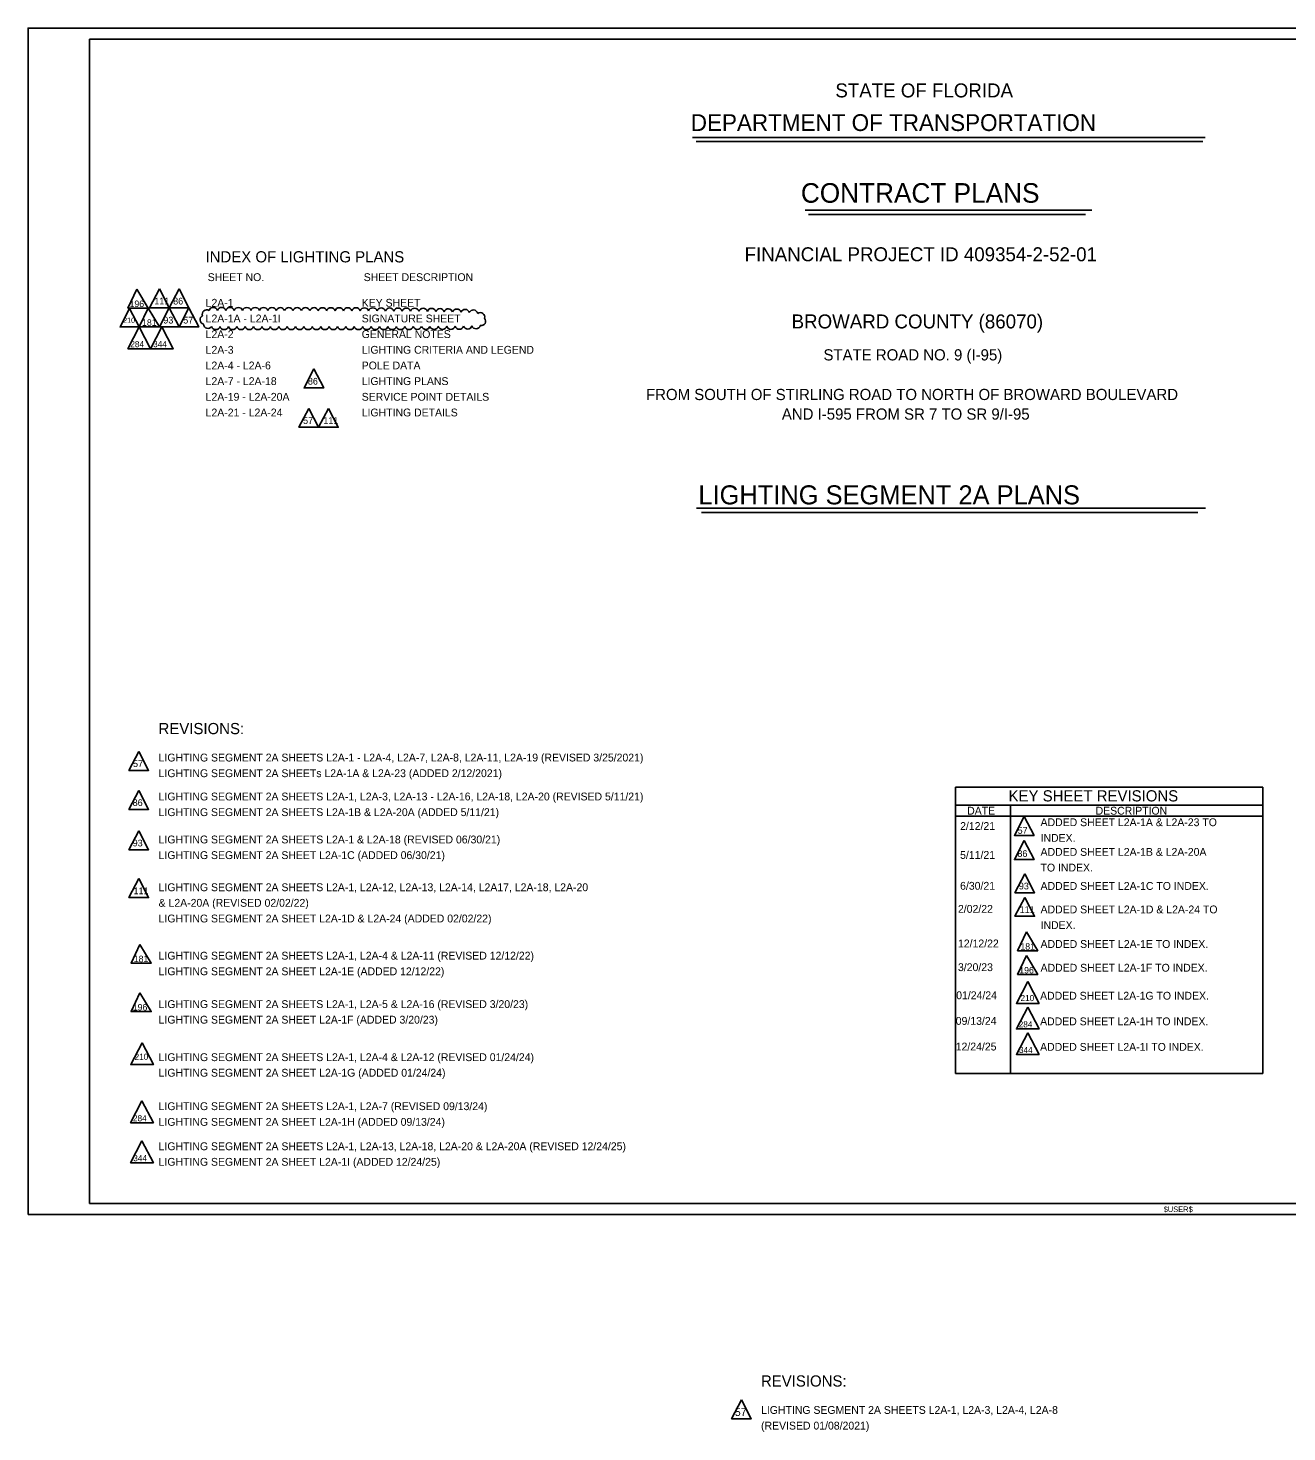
# Model space of a CAD drawing. Extents: x -820.2 to -798.7, y -2201.1 to -2188.5.
# Drawn here: x -820.23 to -808.98, y -2201.07 to -2188.52 of the extents above; entities that cross this region are included whole.
import ezdxf

# ---------------------------------------------------------------- set-up
doc = ezdxf.new("R2010")
doc.units = 0
for name, color, linetype in [('AdhocPoint_dp', 7, 'Continuous'), ('Cloud_dp', 7, 'Continuous'), ('PlotBorder_dp', 7, 'Continuous'), ('SheetBorder_dp', 7, 'Continuous'), ('SumBoxLines_dp', 7, 'Continuous'), ('TextLabel', 7, 'Continuous'), ('TextMinor', 7, 'Continuous'), ('TextNotes', 7, 'Continuous'), ('TextTitle', 7, 'Continuous')]:
    doc.layers.add(name, color=color, linetype=linetype)

msp = doc.modelspace()

# ---------------------------------------------------------------- linework, layer by layer
at = {"layer": 'AdhocPoint_dp'}
msp.add_line((-820.227, -2199.124), (-820.227, -2199.124), dxfattribs=at)
at = {"layer": 'Cloud_dp'}
for points in [[(-819.256, -2190.857), (-819.335, -2191.025), (-819.155, -2191.025)], [(-819.053, -2190.854), (-819.141, -2191.023), (-818.965, -2191.023)], [(-818.877, -2190.854), (-818.965, -2191.023), (-818.789, -2191.023)], [(-819.319, -2191.028), (-819.405, -2191.193), (-819.234, -2191.193)], [(-819.155, -2191.025), (-819.234, -2191.193), (-819.053, -2191.193)], [(-818.965, -2191.023), (-819.053, -2191.193), (-818.877, -2191.193)], [(-818.789, -2191.023), (-818.877, -2191.193), (-818.701, -2191.193)], [(-819.234, -2191.193), (-819.335, -2191.388), (-819.132, -2191.388)], [(-819.031, -2191.193), (-819.132, -2191.388), (-818.93, -2191.388)], [(-817.672, -2191.569), (-817.76, -2191.739), (-817.584, -2191.739)], [(-817.718, -2191.921), (-817.806, -2192.09), (-817.63, -2192.09)], [(-817.542, -2191.921), (-817.63, -2192.09), (-817.454, -2192.09)], [(-819.238, -2194.986), (-819.326, -2195.156), (-819.15, -2195.156)], [(-819.238, -2195.335), (-819.326, -2195.504), (-819.15, -2195.504)], [(-811.324, -2195.567), (-811.412, -2195.736), (-811.236, -2195.736)], [(-819.238, -2195.696), (-819.326, -2195.865), (-819.15, -2195.865)], [(-811.324, -2195.783), (-811.412, -2195.953), (-811.236, -2195.953)], [(-811.319, -2196.08), (-811.407, -2196.249), (-811.231, -2196.249)], [(-819.238, -2196.123), (-819.326, -2196.292), (-819.15, -2196.292)], [(-811.319, -2196.29), (-811.407, -2196.459), (-811.231, -2196.459)], [(-819.228, -2196.71), (-819.307, -2196.878), (-819.126, -2196.878)], [(-811.305, -2196.599), (-811.384, -2196.767), (-811.203, -2196.767)], [(-811.305, -2196.811), (-811.384, -2196.979), (-811.203, -2196.979)], [(-811.293, -2197.042), (-811.394, -2197.237), (-811.191, -2197.237)], [(-819.228, -2197.142), (-819.307, -2197.31), (-819.126, -2197.31)], [(-811.293, -2197.27), (-811.394, -2197.465), (-811.191, -2197.465)], [(-819.207, -2197.589), (-819.309, -2197.784), (-819.106, -2197.784)], [(-811.293, -2197.499), (-811.394, -2197.694), (-811.191, -2197.694)], [(-819.209, -2198.109), (-819.31, -2198.304), (-819.107, -2198.304)], [(-819.209, -2198.466), (-819.31, -2198.661), (-819.107, -2198.661)], [(-813.851, -2200.779), (-813.939, -2200.949), (-813.763, -2200.949)]]:
    msp.add_lwpolyline(points, close=True, dxfattribs=at)
for centre, radius, start, end in [((-818.631, -2191.079), 0.0393, 57.4429, 202.4429), ((-818.572, -2191.058), 0.0393, 17.4254, 162.4254), ((-818.497, -2191.058), 0.0393, 17.3487, 162.3487), ((-818.422, -2191.058), 0.0393, 17.3487, 162.3487), ((-818.347, -2191.059), 0.0393, 17.3487, 162.3487), ((-818.272, -2191.059), 0.0393, 17.3487, 162.3487), ((-818.197, -2191.059), 0.0393, 17.3487, 162.3487), ((-818.122, -2191.059), 0.0393, 17.3487, 162.3487), ((-818.047, -2191.059), 0.0393, 17.3487, 162.3487), ((-817.972, -2191.06), 0.0393, 17.3487, 162.3487), ((-817.897, -2191.06), 0.0393, 17.3487, 162.3487), ((-817.822, -2191.06), 0.0393, 17.3487, 162.3487), ((-817.747, -2191.06), 0.0393, 17.3487, 162.3487), ((-817.671, -2191.06), 0.0393, 17.3487, 162.3487), ((-817.596, -2191.061), 0.0393, 17.3487, 162.3487), ((-817.521, -2191.061), 0.0393, 17.3487, 162.3487), ((-817.446, -2191.061), 0.0393, 17.3487, 162.3487), ((-817.371, -2191.061), 0.0393, 17.3304, 162.3304), ((-817.296, -2191.061), 0.0393, 17.2888, 162.2888), ((-817.221, -2191.062), 0.0393, 17.2428, 162.2428), ((-817.146, -2191.062), 0.0393, 17.1914, 162.1914), ((-817.071, -2191.063), 0.0393, 17.1336, 162.1336), ((-816.996, -2191.063), 0.0393, 17.0679, 162.0679), ((-816.921, -2191.064), 0.0393, 16.9923, 161.9923), ((-816.846, -2191.064), 0.0393, 16.904, 161.904), ((-816.771, -2191.065), 0.0393, 16.799, 161.799), ((-816.696, -2191.066), 0.0393, 16.6713, 161.6713), ((-816.621, -2191.067), 0.0393, 16.5114, 161.5114), ((-816.546, -2191.069), 0.0393, 16.3028, 161.3028), ((-816.471, -2191.071), 0.0393, 16.0143, 161.0143), ((-816.396, -2191.073), 0.0393, 15.5766, 160.5766), ((-816.321, -2191.076), 0.0393, 14.7862, 159.7862), ((-816.247, -2191.081), 0.0394, 12.403, 157.403), ((-816.185, -2191.104), 0.0393, 341.3099, 126.3099), ((-818.651, -2191.13), 0.0393, 113.8298, 258.8298), ((-818.619, -2191.168), 0.0393, 180.98, 325.98), ((-818.549, -2191.178), 0.0393, 197.5, 342.5), ((-818.474, -2191.178), 0.0393, 197.5, 342.5), ((-818.399, -2191.178), 0.0393, 197.5, 342.5), ((-818.324, -2191.178), 0.0393, 197.5, 342.5), ((-818.249, -2191.178), 0.0393, 197.5, 342.5), ((-818.174, -2191.178), 0.0393, 197.5, 342.5), ((-818.099, -2191.178), 0.0393, 197.5, 342.5), ((-818.024, -2191.178), 0.0393, 197.5, 342.5), ((-817.949, -2191.178), 0.0393, 197.5, 342.5), ((-817.874, -2191.178), 0.0393, 197.5, 342.5), ((-817.799, -2191.178), 0.0393, 197.5, 342.5), ((-817.724, -2191.178), 0.0393, 197.5, 342.5), ((-817.649, -2191.178), 0.0393, 197.5, 342.5), ((-817.574, -2191.178), 0.0393, 197.5, 342.5), ((-817.499, -2191.178), 0.0393, 197.5, 342.5), ((-817.424, -2191.178), 0.0393, 197.5, 342.5), ((-817.349, -2191.178), 0.0393, 197.5052, 342.5052), ((-817.274, -2191.178), 0.0393, 197.5223, 342.5223), ((-817.199, -2191.178), 0.0393, 197.5417, 342.5417), ((-817.123, -2191.178), 0.0393, 197.5633, 342.5633), ((-817.048, -2191.178), 0.0393, 197.5876, 342.5876), ((-816.973, -2191.178), 0.0393, 197.6153, 342.6153), ((-816.898, -2191.178), 0.0393, 197.6471, 342.6471), ((-816.823, -2191.178), 0.0393, 197.6843, 342.6843), ((-816.748, -2191.177), 0.0393, 197.7285, 342.7285), ((-816.673, -2191.177), 0.0393, 197.7822, 342.7822), ((-816.598, -2191.177), 0.0393, 197.8496, 342.8496), ((-816.523, -2191.176), 0.0393, 197.9376, 342.9376), ((-816.448, -2191.176), 0.0393, 198.0595, 343.0595), ((-816.373, -2191.175), 0.0393, 198.2448, 343.2448), ((-816.298, -2191.173), 0.0393, 198.5811, 343.5811), ((-816.223, -2191.171), 0.0394, 199.6227, 344.6227), ((-816.177, -2191.143), 0.0393, 257.5478, 42.5478)]:
    msp.add_arc(centre, radius, start, end, dxfattribs=at)
at = {"layer": 'PlotBorder_dp'}
msp.add_lwpolyline([(-820.227, -2199.124), (-803.727, -2199.124), (-803.727, -2188.524), (-820.227, -2188.524)], close=True, dxfattribs=at)
at = {"layer": 'SheetBorder_dp'}
for p, q in [((-819.677, -2188.624), (-819.677, -2199.024)), ((-819.677, -2188.624), (-804.277, -2188.624)), ((-819.677, -2199.024), (-804.277, -2199.024))]:
    msp.add_line(p, q, dxfattribs=at)
at = {"layer": 'SumBoxLines_dp'}
for p, q in [((-811.938, -2195.306), (-811.938, -2197.863)), ((-811.938, -2195.306), (-809.191, -2195.306)), ((-809.191, -2195.306), (-809.191, -2197.863)), ((-811.938, -2195.466), (-809.191, -2195.466)), ((-811.938, -2195.566), (-809.191, -2195.566)), ((-811.448, -2195.466), (-811.448, -2197.863)), ((-811.938, -2197.863), (-809.191, -2197.863))]:
    msp.add_line(p, q, dxfattribs=at)
at = {"layer": 'TextTitle'}
for p, q in [((-814.289, -2189.5), (-809.707, -2189.5)), ((-814.257, -2189.538), (-809.729, -2189.538)), ((-813.281, -2190.15), (-810.719, -2190.15)), ((-813.253, -2190.188), (-810.777, -2190.188)), ((-814.252, -2192.813), (-809.704, -2192.813)), ((-814.209, -2192.851), (-809.772, -2192.851))]:
    msp.add_line(p, q, dxfattribs=at)

# ---------------------------------------------------------------- texts
at = {"layer": 'Cloud_dp'}
for s, height, p in [('111', 0.06, (-819.099, -2190.993)), ('86', 0.06, (-818.93, -2190.993)), ('93', 0.06, (-819.018, -2191.163)), ('57', 0.06, (-818.84, -2191.163)), ('86', 0.06, (-817.726, -2191.709)), ('57', 0.06, (-817.769, -2192.06)), ('111', 0.06, (-817.588, -2192.06)), ('57', 0.06, (-819.289, -2195.126)), ('86', 0.06, (-819.292, -2195.474)), ('57', 0.06, (-811.383, -2195.722)), ('93', 0.06, (-819.292, -2195.835)), ('86', 0.06, (-811.385, -2195.929)), ('111', 0.06, (-819.284, -2196.262)), ('93', 0.06, (-811.372, -2196.219)), ('111', 0.06, (-811.364, -2196.429)), ('57', 0.07, (-813.91, -2200.924))]:
    msp.add_text(s, height=height, rotation=0, dxfattribs=at).set_placement(p)
for s, height, p in [('196', 0.0582, (-819.32, -2191.016)), ('210', 0.0461, (-819.377, -2191.157)), ('181', 0.0582, (-819.208, -2191.184)), ('284', 0.0547, (-819.313, -2191.375)), ('344', 0.0547, (-819.109, -2191.375)), ('181', 0.0582, (-811.358, -2196.758)), ('181', 0.0582, (-819.282, -2196.869)), ('196', 0.0582, (-811.368, -2196.97)), ('210', 0.0547, (-811.357, -2197.217)), ('196', 0.0582, (-819.291, -2197.301)), ('284', 0.0547, (-811.373, -2197.452)), ('210', 0.0547, (-819.275, -2197.742)), ('344', 0.0547, (-811.371, -2197.681)), ('284', 0.0547, (-819.289, -2198.291)), ('344', 0.0547, (-819.287, -2198.648))]:
    msp.add_text(s, height=height, dxfattribs=at).set_placement(p)
at = {"layer": 'TextLabel'}
for s, height, p in [('INDEX OF LIGHTING PLANS', 0.1, (-818.641, -2190.617)), ('FINANCIAL PROJECT ID 409354-2-52-01', 0.125, (-813.823, -2190.607)), ('L2A-1', 0.07, (-818.64, -2191.013)), ('KEY SHEET', 0.07, (-817.245, -2191.013)), ('L2A-1A - L2A-1I', 0.07, (-818.64, -2191.153)), ('SIGNATURE SHEET', 0.07, (-817.245, -2191.153)), ('BROWARD COUNTY (86070)', 0.125, (-813.403, -2191.207)), ('L2A-2', 0.07, (-818.64, -2191.293)), ('GENERAL NOTES', 0.07, (-817.245, -2191.293)), ('L2A-3', 0.07, (-818.64, -2191.433)), ('LIGHTING CRITERIA AND LEGEND', 0.07, (-817.245, -2191.433)), ('STATE ROAD NO. 9 (I-95)', 0.1, (-813.118, -2191.493)), ('L2A-4 - L2A-6 ', 0.07, (-818.64, -2191.573)), ('POLE DATA', 0.07, (-817.245, -2191.573)), ('L2A-7 - L2A-18', 0.07, (-818.64, -2191.713)), ('LIGHTING PLANS', 0.07, (-817.245, -2191.713)), ('L2A-19 - L2A-20A', 0.07, (-818.64, -2191.853)), ('SERVICE POINT DETAILS', 0.07, (-817.245, -2191.853)), ('FROM SOUTH OF STIRLING ROAD TO NORTH OF BROWARD BOULEVARD', 0.1, (-814.704, -2191.847)), ('L2A-21 - L2A-24', 0.07, (-818.64, -2191.993)), ('LIGHTING DETAILS', 0.07, (-817.245, -2191.993)), ('AND I-595 FROM SR 7 TO SR 9/I-95', 0.1, (-813.49, -2192.022)), ('REVISIONS:', 0.1, (-819.061, -2194.832)), ('KEY SHEET REVISIONS', 0.1, (-811.464, -2195.433)), ('REVISIONS:', 0.1, (-813.677, -2200.661))]:
    msp.add_text(s, height=height, dxfattribs=at).set_placement(p)
at = {"layer": 'TextMinor'}
for s, height, p in [('ADDED SHEET L2A-1A & L2A-23 TO ', 0.07, (-811.178, -2195.654)), ('2/12/21', 0.07, (-811.897, -2195.688)), ('INDEX.', 0.07, (-811.178, -2195.794)), ('5/11/21', 0.07, (-811.897, -2195.946)), ('ADDED SHEET L2A-1B & L2A-20A ', 0.07, (-811.178, -2195.919)), ('TO INDEX.', 0.07, (-811.178, -2196.059)), ('6/30/21', 0.07, (-811.897, -2196.222)), ('ADDED SHEET L2A-1C TO INDEX.', 0.07, (-811.178, -2196.223)), ('2/02/22', 0.07, (-811.916, -2196.428)), ('ADDED SHEET L2A-1D & L2A-24 TO ', 0.07, (-811.178, -2196.433)), ('INDEX.', 0.07, (-811.178, -2196.573)), ('12/12/22', 0.07, (-811.916, -2196.737)), ('ADDED SHEET L2A-1E TO INDEX.', 0.07, (-811.178, -2196.742)), ('3/20/23', 0.07, (-811.916, -2196.949)), ('ADDED SHEET L2A-1F TO INDEX.', 0.07, (-811.178, -2196.954)), ('01/24/24', 0.07, (-811.932, -2197.2)), ('ADDED SHEET L2A-1G TO INDEX.', 0.07, (-811.182, -2197.204)), ('09/13/24', 0.07, (-811.936, -2197.429)), ('ADDED SHEET L2A-1H TO INDEX.', 0.07, (-811.182, -2197.433)), ('12/24/25', 0.07, (-811.936, -2197.658)), ('ADDED SHEET L2A-1I TO INDEX.', 0.07, (-811.182, -2197.661)), ('$USER$', 0.05, (-810.078, -2199.102))]:
    msp.add_text(s, height=height, dxfattribs=at).set_placement(p)
at = {"layer": 'TextNotes'}
for s, height, p in [('SHEET NO.', 0.07, (-818.621, -2190.784)), ('SHEET DESCRIPTION', 0.07, (-817.227, -2190.784)), ('LIGHTING SEGMENT 2A SHEETS L2A-1 - L2A-4, L2A-7, L2A-8, L2A-11, L2A-19 (REVISED 3/25/2021)', 0.06998, (-819.06, -2195.076)), ('LIGHTING SEGMENT 2A SHEETs L2A-1A & L2A-23 (ADDED 2/12/2021)', 0.06998, (-819.06, -2195.216)), ('LIGHTING SEGMENT 2A SHEETS L2A-1, L2A-3, L2A-13 - L2A-16, L2A-18, L2A-20 (REVISED 5/11/21)', 0.06998, (-819.06, -2195.424)), ('LIGHTING SEGMENT 2A SHEETS L2A-1B & L2A-20A (ADDED 5/11/21)', 0.06998, (-819.06, -2195.564)), ('DATE', 0.07, (-811.834, -2195.551)), ('DESCRIPTION', 0.07, (-810.686, -2195.551)), ('LIGHTING SEGMENT 2A SHEETS L2A-1 & L2A-18 (REVISED 06/30/21)', 0.06998, (-819.06, -2195.808)), ('LIGHTING SEGMENT 2A SHEET L2A-1C (ADDED 06/30/21)', 0.06998, (-819.06, -2195.948)), ('LIGHTING SEGMENT 2A SHEETS L2A-1, L2A-12, L2A-13, L2A-14, L2A17, L2A-18, L2A-20 ', 0.06998, (-819.06, -2196.235)), ('& L2A-20A (REVISED 02/02/22)', 0.06998, (-819.06, -2196.374)), ('LIGHTING SEGMENT 2A SHEET L2A-1D & L2A-24 (ADDED 02/02/22)', 0.06998, (-819.06, -2196.514)), ('LIGHTING SEGMENT 2A SHEETS L2A-1, L2A-4 & L2A-11 (REVISED 12/12/22)', 0.06998, (-819.06, -2196.846)), ('LIGHTING SEGMENT 2A SHEET L2A-1E (ADDED 12/12/22)', 0.06998, (-819.06, -2196.986)), ('LIGHTING SEGMENT 2A SHEETS L2A-1, L2A-5 & L2A-16 (REVISED 3/20/23)', 0.06998, (-819.06, -2197.279)), ('LIGHTING SEGMENT 2A SHEET L2A-1F (ADDED 3/20/23)', 0.06998, (-819.06, -2197.418)), ('LIGHTING SEGMENT 2A SHEETS L2A-1, L2A-4 & L2A-12 (REVISED 01/24/24)', 0.06998, (-819.06, -2197.753)), ('LIGHTING SEGMENT 2A SHEET L2A-1G (ADDED 01/24/24)', 0.06998, (-819.06, -2197.892)), ('LIGHTING SEGMENT 2A SHEETS L2A-1, L2A-7 (REVISED 09/13/24)', 0.06998, (-819.06, -2198.191)), ('LIGHTING SEGMENT 2A SHEET L2A-1H (ADDED 09/13/24)', 0.06998, (-819.06, -2198.331)), ('LIGHTING SEGMENT 2A SHEETS L2A-1, L2A-13, L2A-18, L2A-20 & L2A-20A (REVISED 12/24/25)', 0.06998, (-819.06, -2198.549)), ('LIGHTING SEGMENT 2A SHEET L2A-1I (ADDED 12/24/25)', 0.06998, (-819.06, -2198.688)), ('LIGHTING SEGMENT 2A SHEETS L2A-1, L2A-3, L2A-4, L2A-8 ', 0.07, (-813.676, -2200.905)), ('(REVISED 01/08/2021)', 0.07, (-813.676, -2201.045))]:
    msp.add_text(s, height=height, dxfattribs=at).set_placement(p)
at = {"layer": 'TextTitle'}
for s, height, p in [('STATE OF FLORIDA', 0.125, (-813.012, -2189.143)), ('DEPARTMENT OF TRANSPORTATION', 0.15, (-814.304, -2189.443)), ('CONTRACT PLANS', 0.175, (-813.32, -2190.084)), ('LIGHTING SEGMENT 2A PLANS', 0.17, (-814.236, -2192.779))]:
    msp.add_text(s, height=height, dxfattribs=at).set_placement(p)

doc.saveas('drawing.dxf')
